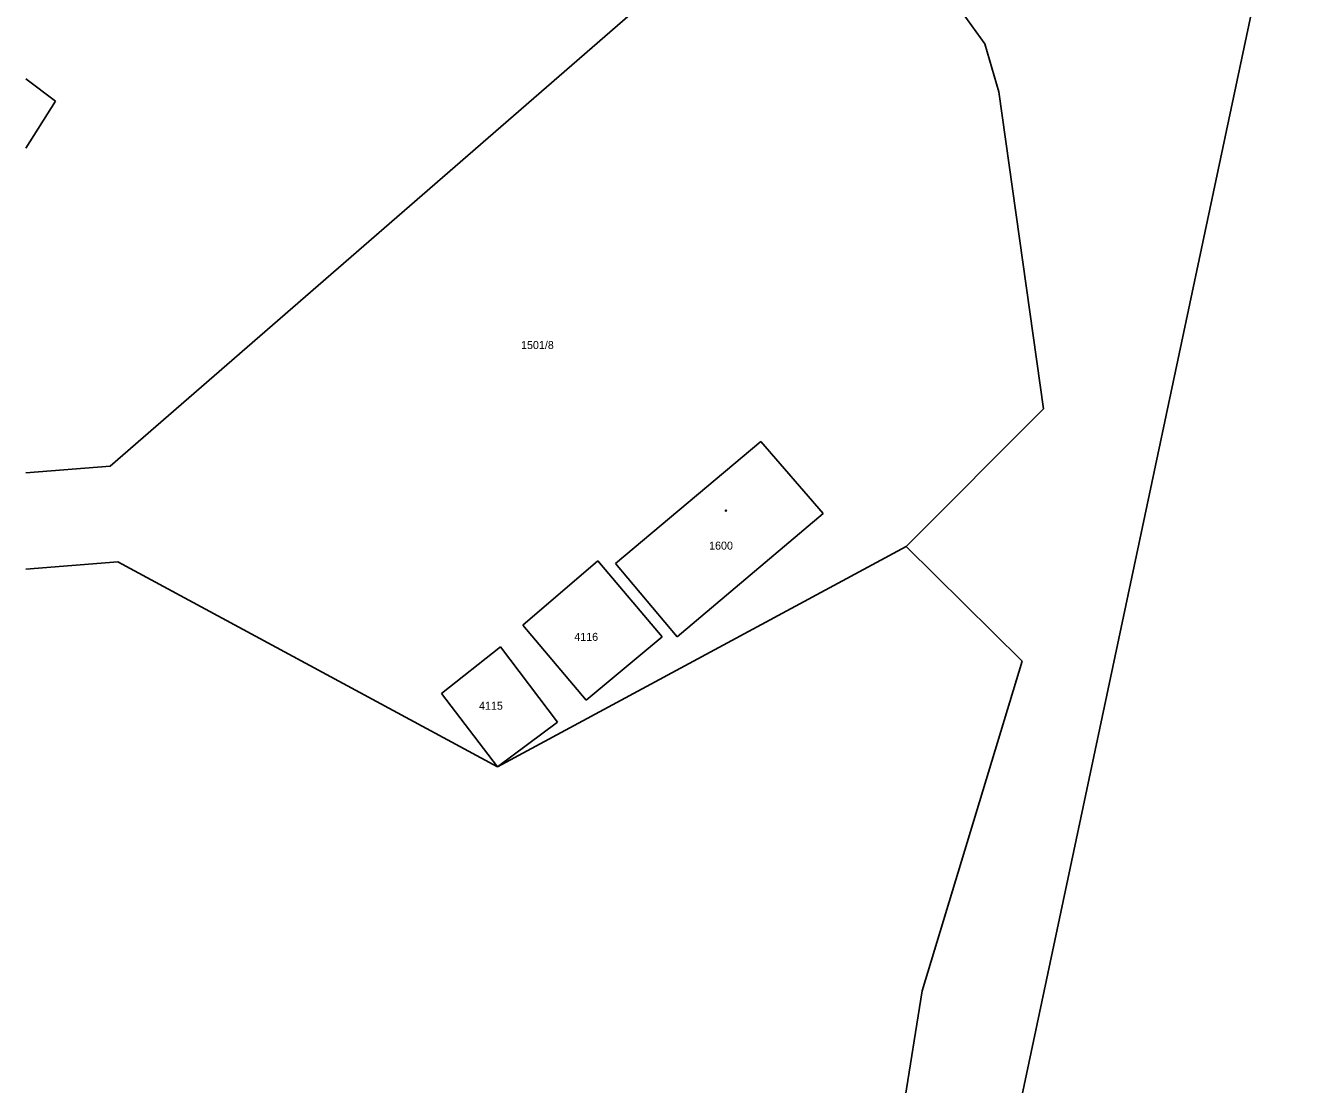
# Model space of a CAD drawing. Extents: x -866624 to -866276, y -1050208 to -1049940.
# Drawn here: x -866623.7 to -866543.1, y -1050140.5 to -1050074.4 of the extents above; entities that cross this region are included whole.
import ezdxf

# ---------------------------------------------------------------- set-up
doc = ezdxf.new("R2010")
doc.units = 0
for name, color, linetype in [('Default', 7, 'Continuous'), ('Hranice', 7, 'Continuous'), ('Hranice-budov', 7, 'Continuous'), ('Parcela-pozemkova', 7, 'Continuous'), ('Parcela-stavebni', 7, 'Continuous'), ('znacky-budov', 7, 'Continuous')]:
    doc.layers.add(name, color=color, linetype=linetype)

# ---------------------------------------------------------------- blocks, each defined once
blk = doc.blocks.new('s_zdena')
at = {"layer": 'Default'}
blk.add_circle((0, 0), 0.175, dxfattribs=at)
for start, end in [(0, 180), (180, 0)]:
    blk.add_arc((0, 0), 0.0875, start, end, dxfattribs=at)

msp = doc.modelspace()

# ---------------------------------------------------------------- linework, layer by layer
at = {"layer": 'Hranice'}
for p, q in [((-866565.77, -1050161.24), (-866543.07, -1050054.21)), ((-866618.46, -1050101.87), (-866582.91, -1050070.98)), ((-866563.83, -1050075.48), (-866565.46, -1050073.25)), ((-866562.96, -1050078.49), (-866563.83, -1050075.48)), ((-866623.725, -1050077.673), (-866621.87, -1050079.07)), ((-866560.17, -1050098.29), (-866562.96, -1050078.49)), ((-866621.87, -1050079.07), (-866623.725, -1050082.011)), ((-866568.74, -1050106.88), (-866560.17, -1050098.29)), ((-866586.9, -1050107.95), (-866577.81, -1050100.32)), ((-866577.81, -1050100.32), (-866573.92, -1050104.83)), ((-866623.725, -1050102.294), (-866618.46, -1050101.87)), ((-866573.92, -1050104.83), (-866583.04, -1050112.52)), ((-866568.74, -1050106.88), (-866594.26, -1050120.64)), ((-866561.49, -1050114.05), (-866568.74, -1050106.88)), ((-866617.98, -1050107.85), (-866623.725, -1050108.312)), ((-866594.26, -1050120.64), (-866617.98, -1050107.85)), ((-866592.69, -1050111.8), (-866588, -1050107.79)), ((-866588, -1050107.79), (-866583.98, -1050112.53)), ((-866583.04, -1050112.52), (-866586.9, -1050107.95)), ((-866588.73, -1050116.48), (-866592.69, -1050111.8)), ((-866583.98, -1050112.53), (-866588.73, -1050116.48)), ((-866597.77, -1050116.06), (-866594.08, -1050113.15)), ((-866594.08, -1050113.15), (-866590.51, -1050117.87)), ((-866567.75, -1050134.64), (-866561.49, -1050114.05)), ((-866594.26, -1050120.64), (-866597.77, -1050116.06)), ((-866590.51, -1050117.87), (-866594.26, -1050120.64)), ((-866568.88, -1050141.81), (-866567.75, -1050134.64))]:
    msp.add_line(p, q, dxfattribs=at)
at = {"layer": 'Hranice-budov'}
for p, q in [((-866623.725, -1050077.673), (-866621.87, -1050079.07)), ((-866621.87, -1050079.07), (-866623.725, -1050082.011)), ((-866586.9, -1050107.95), (-866577.81, -1050100.32)), ((-866577.81, -1050100.32), (-866573.92, -1050104.83)), ((-866573.92, -1050104.83), (-866583.04, -1050112.52)), ((-866583.04, -1050112.52), (-866586.9, -1050107.95))]:
    msp.add_line(p, q, dxfattribs=at)

# ---------------------------------------------------------------- block references
at = {"layer": 'znacky-budov', "xscale": 0.2, "yscale": 0.20000000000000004}
msp.add_blockref('s_zdena', (-866580, -1050104.65), dxfattribs=at)

# ---------------------------------------------------------------- texts
at = {"layer": 'Parcela-pozemkova'}
for s, p in [('1501/8', (-866592.794, -1050094.553)), ('4116', (-866589.469, -1050112.783)), ('4115', (-866595.419, -1050117.083))]:
    msp.add_text(s, height=0.5, dxfattribs=at).set_placement(p)
at = {"layer": 'Parcela-stavebni'}
msp.add_text('1600', height=0.5, dxfattribs=at).set_placement((-866581.049, -1050107.083))

doc.saveas('drawing.dxf')
